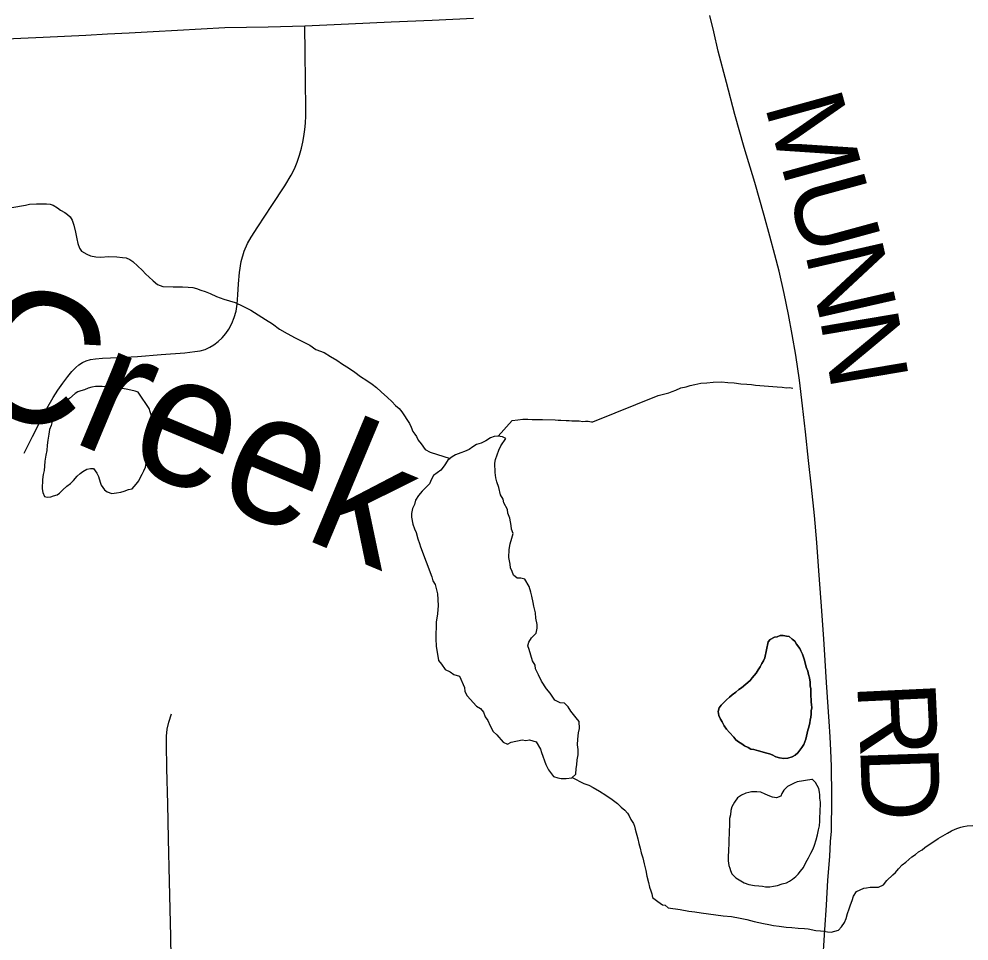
# Model space of a CAD drawing. Extents: x -11.4 to 84.1, y 11.1 to 59.
# Drawn here: x 31.454 to 32.145, y 42.32 to 42.991 of the extents above; entities that cross this region are included whole.
import ezdxf

# ---------------------------------------------------------------- set-up
doc = ezdxf.new("R2010")
doc.units = 0
for name, color, linetype in [('GM_X_Minor_Lake', 7, 'Continuous'), ('GM_X_Minor_River', 7, 'Continuous'), ('GM_X_Minor_River_Text', 7, 'Continuous'), ('GM_X_Township_Road', 7, 'Continuous'), ('GM_X_Township_Road_Text', 7, 'Continuous')]:
    doc.layers.add(name, color=color, linetype=linetype)

msp = doc.modelspace()

# ---------------------------------------------------------------- linework, layer by layer
at = {"layer": 'GM_X_Minor_Lake'}
for points in [[(31.54104, 42.7185), (31.54064, 42.71925), (31.53835, 42.71998), (31.5353, 42.72069), (31.53187, 42.72139), (31.52883, 42.72172), (31.5254, 42.72243), (31.52121, 42.72274), (31.51893, 42.72308), (31.51665, 42.72304), (31.51436, 42.72338), (31.51171, 42.72334), (31.50943, 42.7233), (31.50678, 42.72288), (31.50413, 42.72208), (31.50149, 42.72089), (31.49885, 42.72009), (31.49658, 42.71929), (31.4947, 42.71812), (31.49058, 42.71463), (31.48871, 42.71308), (31.48573, 42.70961), (31.48386, 42.70768), (31.48238, 42.70537), (31.4809, 42.70307), (31.47942, 42.70114), (31.47832, 42.69884), (31.47724, 42.69502), (31.47615, 42.69196), (31.47545, 42.68853), (31.47476, 42.68433), (31.47445, 42.68053), (31.47413, 42.67672), (31.47343, 42.67329), (31.47274, 42.66909), (31.47243, 42.66529), (31.4721, 42.66224), (31.47139, 42.65919), (31.47107, 42.65576), (31.4708, 42.64891), (31.47123, 42.64626), (31.47242, 42.64324), (31.47432, 42.64288), (31.47698, 42.64293), (31.47886, 42.64372)], [(31.54104, 42.7185), (31.54064, 42.71925), (31.53835, 42.71998), (31.5353, 42.72069), (31.53187, 42.72139), (31.52883, 42.72172), (31.5254, 42.72243), (31.52121, 42.72274), (31.51893, 42.72308), (31.51665, 42.72304), (31.51436, 42.72338), (31.51171, 42.72334), (31.50943, 42.7233), (31.50678, 42.72288), (31.50413, 42.72208), (31.50149, 42.72089), (31.49885, 42.72009), (31.49658, 42.71929), (31.4947, 42.71812), (31.49058, 42.71463), (31.48871, 42.71308), (31.48573, 42.70961), (31.48386, 42.70768), (31.48238, 42.70537), (31.4809, 42.70307), (31.47942, 42.70114), (31.47832, 42.69884), (31.47724, 42.69502), (31.47615, 42.69196), (31.47545, 42.68853), (31.47476, 42.68433), (31.47445, 42.68053), (31.47413, 42.67672), (31.47343, 42.67329), (31.47274, 42.66909), (31.47243, 42.66529), (31.4721, 42.66224), (31.47139, 42.65919), (31.47107, 42.65576), (31.4708, 42.64891), (31.47123, 42.64626), (31.47242, 42.64324), (31.47432, 42.64288), (31.47698, 42.64293), (31.47886, 42.64372), (31.48151, 42.64452), (31.48339, 42.64569), (31.48563, 42.64801), (31.48862, 42.65072), (31.49125, 42.65267), (31.49349, 42.65499), (31.4961, 42.65807), (31.49834, 42.66001), (31.50022, 42.66156), (31.50323, 42.66313), (31.50588, 42.66355), (31.50816, 42.66359), (31.51049, 42.66021), (31.51167, 42.65794), (31.51288, 42.65378), (31.51368, 42.65151), (31.51601, 42.64813), (31.51794, 42.64664), (31.52137, 42.64556), (31.52479, 42.64599), (31.52782, 42.64642), (31.53046, 42.64723), (31.53348, 42.64842), (31.53613, 42.64884), (31.53911, 42.65231), (31.54097, 42.65462), (31.54207, 42.65692), (31.54355, 42.65961), (31.54465, 42.66191), (31.54574, 42.66459), (31.54645, 42.66764), (31.54753, 42.67108), (31.54823, 42.67489), (31.54892, 42.67909), (31.54961, 42.6829), (31.54993, 42.68671), (31.55063, 42.68976), (31.5506, 42.69166), (31.55094, 42.69433), (31.55088, 42.69775), (31.55046, 42.7004), (31.55004, 42.70268), (31.54924, 42.70495), (31.54844, 42.70722), (31.54104, 42.7185)], [(31.47886, 42.64372), (31.48151, 42.64452), (31.48339, 42.64569), (31.48563, 42.64801), (31.48862, 42.65072), (31.49125, 42.65267), (31.49349, 42.65499), (31.4961, 42.65807), (31.49834, 42.66001), (31.50022, 42.66156), (31.50323, 42.66313), (31.50588, 42.66355), (31.50816, 42.66359), (31.51049, 42.66021), (31.51167, 42.65794), (31.51288, 42.65378), (31.51368, 42.65151), (31.51601, 42.64813), (31.51794, 42.64664), (31.52137, 42.64556), (31.52479, 42.64599), (31.52782, 42.64642), (31.53046, 42.64723), (31.53348, 42.64842), (31.53613, 42.64884), (31.53911, 42.65231), (31.54097, 42.65462), (31.54207, 42.65692), (31.54355, 42.65961), (31.54465, 42.66191), (31.54574, 42.66459), (31.54645, 42.66764), (31.54753, 42.67108), (31.54823, 42.67489), (31.54892, 42.67909), (31.54961, 42.6829), (31.54993, 42.68671), (31.55063, 42.68976), (31.5506, 42.69166), (31.55094, 42.69433), (31.55088, 42.69775), (31.55046, 42.7004), (31.55004, 42.70268), (31.54924, 42.70495), (31.54844, 42.70722), (31.54104, 42.7185)], [(31.80791, 42.68552), (31.80538, 42.68656), (31.80195, 42.68727), (31.7993, 42.68685), (31.79665, 42.68606), (31.79327, 42.68374), (31.78987, 42.68217), (31.78647, 42.68099), (31.78384, 42.67943), (31.78121, 42.6775), (31.77781, 42.67593), (31.77517, 42.67514), (31.77139, 42.67357), (31.76875, 42.67202), (31.76575, 42.6697), (31.76315, 42.66549), (31.76054, 42.66242), (31.75528, 42.65855), (31.7538, 42.65588), (31.75233, 42.65244), (31.7471, 42.64706), (31.74448, 42.64399), (31.74225, 42.64054), (31.74154, 42.63749), (31.74007, 42.63444), (31.73936, 42.63102), (31.7394, 42.62836), (31.74024, 42.62306), (31.74143, 42.61966), (31.74261, 42.61702), (31.74382, 42.61248), (31.74501, 42.60908), (31.74589, 42.60678)], [(31.75715, 42.5345), (31.75883, 42.5239), (31.76114, 42.52127), (31.76386, 42.51752), (31.76731, 42.51567), (31.76999, 42.51381), (31.77419, 42.51272), (31.77773, 42.50442), (31.77815, 42.5014), (31.77972, 42.49838), (31.78667, 42.49089), (31.78936, 42.48902), (31.79168, 42.4864), (31.79287, 42.483), (31.79481, 42.48037), (31.79638, 42.4766), (31.79872, 42.47246), (31.80142, 42.46984), (31.80606, 42.46459), (31.80912, 42.46311), (31.81176, 42.46467), (31.81971, 42.46629), (31.82237, 42.46595), (31.82503, 42.46637), (31.82999, 42.46492), (31.83311, 42.45965), (31.8339, 42.457), (31.83708, 42.44832), (31.83903, 42.44455), (31.84252, 42.43967), (31.84558, 42.43857), (31.84824, 42.43823), (31.85166, 42.43827), (31.85583, 42.43871), (31.85883, 42.44141), (31.85915, 42.44559), (31.85949, 42.44824), (31.85982, 42.45167), (31.86052, 42.45547), (31.86046, 42.45926), (31.86003, 42.46267), (31.86035, 42.46685), (31.86066, 42.47141), (31.86137, 42.47445), (31.86129, 42.47976), (31.85897, 42.48239), (31.8551, 42.48727), (31.85316, 42.49028), (31.85046, 42.4929), (31.84741, 42.49323), (31.84359, 42.49508), (31.84009, 42.50034), (31.83739, 42.50334), (31.83388, 42.50899), (31.83154, 42.51351), (31.82957, 42.51803), (31.82915, 42.52069), (31.8272, 42.52369), (31.8248, 42.53201), (31.824, 42.53465), (31.82472, 42.53732), (31.82657, 42.54038), (31.82994, 42.54384), (31.83064, 42.54764), (31.8306, 42.5503), (31.82977, 42.55484), (31.82934, 42.55863), (31.82813, 42.56355), (31.82771, 42.5662), (31.82688, 42.57074), (31.82607, 42.57377), (31.82487, 42.57792), (31.82175, 42.58319), (31.8187, 42.58391), (31.81604, 42.58387), (31.81335, 42.58611), (31.81255, 42.58876), (31.81137, 42.5914), (31.81095, 42.59405), (31.81012, 42.59897), (31.81041, 42.60467), (31.81111, 42.60885), (31.81219, 42.61304), (31.81327, 42.61647), (31.81209, 42.61949), (31.81167, 42.62214), (31.81083, 42.62744), (31.80925, 42.63121), (31.80921, 42.63387), (31.80648, 42.63876), (31.80606, 42.64141), (31.80412, 42.64442), (31.8029, 42.64972), (31.80132, 42.65387), (31.80051, 42.65689), (31.80008, 42.66068), (31.79997, 42.66751), (31.80031, 42.67017), (31.80287, 42.67704), (31.80434, 42.68009), (31.80791, 42.68552)], [(31.74589, 42.60678), (31.75411, 42.58492), (31.75491, 42.5819), (31.75647, 42.57926), (31.75809, 42.57246), (31.7586, 42.56412), (31.75831, 42.55804), (31.75726, 42.55195), (31.75706, 42.53981), (31.75715, 42.5345)], [(31.99865, 42.53758), (32.00021, 42.53934), (32.00323, 42.54092), (32.00512, 42.54133), (32.00738, 42.54213), (32.00966, 42.54216), (32.01195, 42.54182), (32.01385, 42.54147), (32.01616, 42.53961), (32.01809, 42.53812), (32.01926, 42.53585), (32.02159, 42.53285), (32.02238, 42.53096), (32.02356, 42.5287), (32.02516, 42.52417), (32.02638, 42.51924), (32.02757, 42.51622), (32.02799, 42.51395), (32.02879, 42.5113), (32.02922, 42.50826), (32.02927, 42.5056), (32.02969, 42.50333), (32.02973, 42.50067), (32.02978, 42.49801), (32.02982, 42.49573), (32.02985, 42.49383), (32.03026, 42.49193), (32.0303, 42.48965), (32.02996, 42.48737), (32.03, 42.48509), (32.02965, 42.4828), (32.02931, 42.48051), (32.02897, 42.4786), (32.02826, 42.47555), (32.02754, 42.47326), (32.02647, 42.46906), (32.02613, 42.46677), (32.0254, 42.46486), (32.02467, 42.46295), (32.02319, 42.46064), (32.02022, 42.45679), (32.01834, 42.45524), (32.01608, 42.45406), (32.01307, 42.45287), (32.01003, 42.45282), (32.00698, 42.45315), (32.00431, 42.45387), (32.00163, 42.45534), (31.99972, 42.45607), (31.99667, 42.45678), (31.99438, 42.45751), (31.99171, 42.45822), (31.98827, 42.45931), (31.98598, 42.45965), (31.98407, 42.46076), (31.98139, 42.46185), (31.97947, 42.46334), (31.97716, 42.46483), (31.97524, 42.46632), (31.97369, 42.46819), (31.97059, 42.47156), (31.96827, 42.47419), (31.96671, 42.47644), (31.96514, 42.47946), (31.96397, 42.48134), (31.96279, 42.48398), (31.96236, 42.48702), (31.96307, 42.48969), (31.96456, 42.49162), (31.96642, 42.49355), (31.96829, 42.49548), (31.97054, 42.49742), (31.97241, 42.49897), (31.97503, 42.50091), (31.97728, 42.50285), (31.97916, 42.50402), (31.98552, 42.50945), (31.98701, 42.51137), (31.98999, 42.51484), (31.99147, 42.51715), (31.99295, 42.51946), (31.99405, 42.52176), (31.99516, 42.52367), (31.99626, 42.52597), (31.99865, 42.53758)], [(32.01608, 42.45406), (32.01834, 42.45524), (32.02022, 42.45679), (32.02319, 42.46064), (32.02467, 42.46295), (32.0254, 42.46486), (32.02613, 42.46677), (32.02647, 42.46906), (32.02754, 42.47326), (32.02826, 42.47555), (32.02897, 42.4786), (32.02931, 42.48051), (32.02965, 42.4828), (32.03, 42.48509), (32.02996, 42.48737), (32.0303, 42.48965), (32.03026, 42.49193), (32.02985, 42.49383), (32.02982, 42.49573), (32.02978, 42.49801), (32.02973, 42.50067), (32.02969, 42.50333), (32.02927, 42.5056), (32.02922, 42.50826), (32.02879, 42.5113), (32.02799, 42.51395), (32.02757, 42.51622), (32.02638, 42.51924), (32.02516, 42.52417), (32.02356, 42.5287), (32.02238, 42.53096), (32.02159, 42.53285), (32.01926, 42.53585), (32.01809, 42.53812), (32.01616, 42.53961), (32.01385, 42.54147), (32.01195, 42.54182), (32.00966, 42.54216), (32.00738, 42.54213), (32.00512, 42.54133), (32.00323, 42.54092), (32.00021, 42.53934), (31.99865, 42.53758)], [(31.99865, 42.53758), (31.99626, 42.52597), (31.99516, 42.52367), (31.99405, 42.52176), (31.99295, 42.51946), (31.99147, 42.51715), (31.98999, 42.51484), (31.98701, 42.51137), (31.98552, 42.50945), (31.97916, 42.50402), (31.97728, 42.50285), (31.97503, 42.50091), (31.97241, 42.49897), (31.97054, 42.49742), (31.96829, 42.49548), (31.96642, 42.49355), (31.96456, 42.49162), (31.96307, 42.48969), (31.96236, 42.48702), (31.96279, 42.48398), (31.96397, 42.48134), (31.96514, 42.47946), (31.96671, 42.47644), (31.96827, 42.47419), (31.97059, 42.47156), (31.97369, 42.46819), (31.97524, 42.46632), (31.97716, 42.46483), (31.97947, 42.46334), (31.98139, 42.46185), (31.98407, 42.46076), (31.98598, 42.45965), (31.98827, 42.45931), (31.99171, 42.45822), (31.99438, 42.45751), (31.99667, 42.45678), (31.99972, 42.45607), (32.00163, 42.45534), (32.00431, 42.45387), (32.00698, 42.45315), (32.01003, 42.45282), (32.01307, 42.45287), (32.01608, 42.45406)], [(32.03042, 42.43757), (32.01981, 42.43587), (32.01755, 42.43469), (32.01567, 42.4339), (32.01265, 42.43233), (32.01004, 42.42963), (32.00856, 42.42732), (32.00783, 42.42541), (32.00481, 42.42422), (32.00177, 42.42455), (31.99986, 42.42528), (31.99642, 42.42674), (31.99335, 42.42821), (31.99031, 42.42854), (31.98651, 42.42848), (31.98462, 42.42807), (31.98235, 42.42765), (31.97933, 42.42608), (31.97633, 42.42413), (31.9741, 42.42105), (31.97226, 42.4176), (31.97155, 42.41493), (31.97122, 42.41188), (31.9705, 42.40921), (31.97054, 42.40693), (31.97059, 42.40389), (31.97027, 42.40046), (31.97004, 42.39171), (31.97008, 42.38943), (31.96973, 42.38752), (31.96977, 42.38524), (31.96945, 42.38182), (31.9695, 42.3784), (31.96994, 42.37498), (31.97073, 42.37309), (31.97115, 42.3712), (31.97232, 42.36894), (31.97503, 42.36594), (31.97887, 42.36372)], [(32.03042, 42.43757), (32.01981, 42.43587), (32.01755, 42.43469), (32.01567, 42.4339), (32.01265, 42.43233), (32.01004, 42.42963), (32.00856, 42.42732), (32.00783, 42.42541), (32.00481, 42.42422), (32.00177, 42.42455), (31.99986, 42.42528), (31.99642, 42.42674), (31.99335, 42.42821), (31.99031, 42.42854), (31.98651, 42.42848), (31.98462, 42.42807), (31.98235, 42.42765), (31.97933, 42.42608), (31.97633, 42.42413), (31.9741, 42.42105), (31.97226, 42.4176), (31.97155, 42.41493), (31.97122, 42.41188), (31.9705, 42.40921), (31.97054, 42.40693), (31.97059, 42.40389), (31.97027, 42.40046), (31.97004, 42.39171), (31.97008, 42.38943), (31.96973, 42.38752), (31.96977, 42.38524), (31.96945, 42.38182), (31.9695, 42.3784), (31.96994, 42.37498), (31.97073, 42.37309), (31.97115, 42.3712), (31.97232, 42.36894), (31.97503, 42.36594), (31.97887, 42.36372), (31.98117, 42.36224), (31.98461, 42.36116), (31.9888, 42.36046), (31.99184, 42.36013), (31.99451, 42.3598), (31.99679, 42.35945), (31.99983, 42.3595), (32.00248, 42.35993), (32.00551, 42.36036), (32.00891, 42.36155), (32.01193, 42.36236), (32.01419, 42.36354), (32.01645, 42.3651), (32.01869, 42.36704), (32.02057, 42.36859), (32.02205, 42.37089), (32.02428, 42.37359), (32.02612, 42.37704), (32.02796, 42.3805), (32.0298, 42.38395), (32.03127, 42.38701), (32.03236, 42.38969), (32.03344, 42.39351), (32.03451, 42.39733), (32.03522, 42.40077), (32.03592, 42.40382), (32.03625, 42.40725), (32.03619, 42.41029), (32.03652, 42.41333), (32.03677, 42.42094), (32.03634, 42.42398), (32.0363, 42.42626), (32.03589, 42.42815), (32.03547, 42.43081), (32.03429, 42.43307), (32.03311, 42.43533), (32.0308, 42.43757), (32.03042, 42.43757)], [(31.97887, 42.36372), (31.98117, 42.36224), (31.98461, 42.36116), (31.9888, 42.36046), (31.99184, 42.36013), (31.99451, 42.3598), (31.99679, 42.35945), (31.99983, 42.3595), (32.00248, 42.35993), (32.00551, 42.36036), (32.00891, 42.36155), (32.01193, 42.36236), (32.01419, 42.36354), (32.01645, 42.3651), (32.01869, 42.36704), (32.02057, 42.36859), (32.02205, 42.37089), (32.02428, 42.37359), (32.02612, 42.37704), (32.02796, 42.3805), (32.0298, 42.38395), (32.03127, 42.38701), (32.03236, 42.38969), (32.03344, 42.39351), (32.03451, 42.39733), (32.03522, 42.40077), (32.03592, 42.40382), (32.03625, 42.40725), (32.03619, 42.41029), (32.03652, 42.41333), (32.03677, 42.42094), (32.03634, 42.42398), (32.0363, 42.42626), (32.03589, 42.42815), (32.03547, 42.43081), (32.03429, 42.43307), (32.03311, 42.43533), (32.0308, 42.43757), (32.03042, 42.43757)]]:
    msp.add_lwpolyline(points, dxfattribs=at)
at = {"layer": 'GM_X_Minor_River'}
for points in [[(31.44874, 42.85348), (31.45859, 42.85517), (31.46161, 42.85598), (31.46655, 42.85606), (31.47377, 42.85617), (31.47643, 42.85584), (31.47872, 42.85512), (31.48179, 42.85327), (31.4841, 42.8514), (31.48717, 42.84993), (31.48909, 42.84844), (31.49102, 42.84657), (31.49258, 42.84432), (31.49378, 42.84053), (31.495, 42.83561), (31.49584, 42.83068), (31.49666, 42.82727), (31.49786, 42.82387), (31.49941, 42.82162), (31.50325, 42.8194), (31.50593, 42.8183), (31.50974, 42.8176), (31.51316, 42.81728), (31.51923, 42.81776), (31.52493, 42.81747), (31.52912, 42.81716), (31.53178, 42.81682), (31.53446, 42.81573), (31.53676, 42.81424), (31.54024, 42.81088), (31.54333, 42.80789), (31.54603, 42.80489), (31.54835, 42.80303), (31.55143, 42.80004), (31.55452, 42.79742), (31.55834, 42.79597), (31.56594, 42.79571), (31.56936, 42.79577), (31.57277, 42.79582), (31.57696, 42.79551), (31.58038, 42.79519), (31.58305, 42.79447), (31.58611, 42.79338), (31.58917, 42.79229), (31.59299, 42.79083), (31.59758, 42.78863), (31.60293, 42.78681), (31.61095, 42.78428), (31.61669, 42.78172), (31.62244, 42.77877), (31.62781, 42.77543), (31.63318, 42.7721), (31.63818, 42.76876), (31.64318, 42.76504), (31.64893, 42.76171), (31.65468, 42.75876), (31.66043, 42.75582), (31.66541, 42.75324), (31.66964, 42.75027), (31.67575, 42.74808), (31.68036, 42.74512), (31.68496, 42.74253), (31.68918, 42.73956), (31.69341, 42.73697), (31.69802, 42.73362), (31.70225, 42.73065), (31.70686, 42.72768), (31.7107, 42.72508), (31.71378, 42.72247), (31.71725, 42.71949), (31.72188, 42.71538), (31.72497, 42.71239), (31.72768, 42.70939), (31.73037, 42.70716), (31.73231, 42.70491), (31.73426, 42.7019), (31.73582, 42.69926), (31.73777, 42.69625), (31.73896, 42.69361), (31.74015, 42.69059), (31.7417, 42.68871), (31.74287, 42.68683), (31.74405, 42.68419), (31.74638, 42.68156), (31.74911, 42.67743), (31.75293, 42.67559), (31.76732, 42.6709)], [(31.87106, 42.69768), (31.9186, 42.7167), (31.92352, 42.71792), (31.92654, 42.71874), (31.92881, 42.71953), (31.93145, 42.72072), (31.93522, 42.7223), (31.939, 42.72312), (31.94203, 42.72393), (31.94543, 42.72475), (31.9496, 42.72558), (31.95415, 42.72603), (31.9587, 42.72649), (31.96477, 42.72659), (31.96933, 42.72628), (31.9739, 42.72597), (31.97885, 42.7253), (31.98303, 42.72499), (31.98645, 42.72466), (31.9895, 42.72433), (31.99254, 42.724), (32.00205, 42.72339), (32.00509, 42.72306), (32.0089, 42.72275), (32.01194, 42.72242), (32.01422, 42.72245), (32.0165, 42.72211)], [(31.80228, 42.6872), (31.81256, 42.69862), (31.81673, 42.69906), (31.82014, 42.6995), (31.82394, 42.69956), (31.82698, 42.69924), (31.8304, 42.69929), (31.83457, 42.69936), (31.84369, 42.69913), (31.84598, 42.69878), (31.84788, 42.69882), (31.85168, 42.6985), (31.85396, 42.69853), (31.85586, 42.69819), (31.85776, 42.69822), (31.86118, 42.69827), (31.86384, 42.69794), (31.86574, 42.69797), (31.86764, 42.698), (31.8703, 42.69766), (31.87106, 42.69768)], [(31.85616, 42.439), (31.86449, 42.43446), (31.86831, 42.43339), (31.87137, 42.43154), (31.87598, 42.42895), (31.88058, 42.42599), (31.88519, 42.42302), (31.88904, 42.42004), (31.89174, 42.41742), (31.89444, 42.41518), (31.89638, 42.41294), (31.89755, 42.41106), (31.89873, 42.40841), (31.90068, 42.4054), (31.90147, 42.40352), (31.90189, 42.40124), (31.9039, 42.39443), (31.90472, 42.39102), (31.90554, 42.38761), (31.90636, 42.3842), (31.90756, 42.38042), (31.90839, 42.37625), (31.90961, 42.37133), (31.91044, 42.36716), (31.91166, 42.36262), (31.91248, 42.35921), (31.91328, 42.35656), (31.91408, 42.35429), (31.9145, 42.35164), (31.91835, 42.34866), (31.92181, 42.34644), (31.92371, 42.34609), (31.92602, 42.34422), (31.93478, 42.34285), (31.94088, 42.34181), (31.94544, 42.34112), (31.95001, 42.34044), (31.95534, 42.33976), (31.96067, 42.33909), (31.966, 42.33842), (31.97209, 42.33776), (31.97818, 42.33672), (31.98314, 42.33566), (31.98848, 42.33422), (31.99534, 42.33282), (31.99915, 42.33212), (32.00258, 42.33141), (32.00677, 42.33072), (32.01172, 42.33004), (32.0159, 42.32973), (32.02047, 42.32942), (32.02503, 42.32912), (32.02769, 42.32878), (32.03341, 42.32774), (32.03683, 42.32741), (32.03912, 42.32707), (32.04178, 42.32673), (32.04445, 42.3264), (32.04974, 42.328), (32.05198, 42.33032), (32.0542, 42.3334), (32.05529, 42.33646), (32.05637, 42.3399), (32.05746, 42.34334), (32.05854, 42.3464), (32.05963, 42.34946), (32.06072, 42.35252), (32.06294, 42.35598), (32.06558, 42.35716), (32.06822, 42.35834), (32.07011, 42.35875), (32.07276, 42.35918), (32.07504, 42.35922), (32.07694, 42.35925), (32.07883, 42.35928), (32.08261, 42.36086), (32.08483, 42.36394), (32.08932, 42.3682), (32.09119, 42.36975), (32.09343, 42.37245), (32.09603, 42.37553), (32.09866, 42.37747), (32.1009, 42.37941), (32.10315, 42.38135), (32.10578, 42.38291), (32.10803, 42.38485), (32.11066, 42.38642), (32.11253, 42.38797), (32.1223, 42.39459), (32.12568, 42.39655), (32.12907, 42.3985), (32.13208, 42.40007), (32.13472, 42.40126), (32.13661, 42.40205), (32.13887, 42.40284), (32.14076, 42.40326), (32.14341, 42.40368), (32.14758, 42.40413)]]:
    msp.add_lwpolyline(points, dxfattribs=at)
at = {"layer": 'GM_X_Township_Road'}
for points in [[(31.43912, 42.9758), (31.45526, 42.97651), (31.47138, 42.97722), (31.5024, 42.97889), (31.51814, 42.97974), (31.53387, 42.98058), (31.55151, 42.98154), (31.56915, 42.98249), (31.58636, 42.98339), (31.60356, 42.98429), (31.61935, 42.98462), (31.63513, 42.98495), (31.66176, 42.98563), (31.67762, 42.98628), (31.69349, 42.98692), (31.72453, 42.98836), (31.7544, 42.98976), (31.78427, 42.99114)], [(32.03815, 42.30159), (32.03991, 42.32813), (32.04103, 42.34618), (32.04215, 42.36423), (32.04352, 42.3814), (32.0441, 42.39242), (32.04459, 42.39984), (32.04479, 42.40764), (32.04489, 42.41506), (32.04499, 42.4252), (32.04459, 42.44725), (32.0442, 42.45866), (32.04364, 42.46861), (32.04302, 42.47974), (32.04108, 42.50813), (32.0401, 42.52393), (32.03913, 42.53973), (32.03717, 42.56667), (32.03561, 42.5893), (32.03396, 42.60988), (32.0323, 42.62949), (32.03025, 42.65008), (32.0281, 42.66939), (32.02586, 42.69027), (32.02372, 42.70929), (32.02137, 42.72783), (32.01874, 42.74597), (32.0161, 42.761), (32.01338, 42.77573), (32.01035, 42.79085), (32.00664, 42.80724), (32.00352, 42.81915), (31.99991, 42.83251), (31.99582, 42.84756), (31.98904, 42.87175), (31.98128, 42.89709), (31.97435, 42.921), (31.9683, 42.94431), (31.96225, 42.96724), (31.95913, 42.98109), (31.9562, 42.99319)], [(31.45755, 42.6749), (31.46363, 42.68694), (31.47412, 42.70721), (31.47865, 42.71532), (31.48219, 42.7206), (31.48568, 42.7257), (31.48926, 42.73053), (31.49239, 42.73428), (31.49516, 42.73714), (31.49739, 42.73911), (31.50007, 42.74072), (31.50276, 42.74206), (31.50598, 42.74295), (31.50955, 42.74349), (31.51456, 42.74385), (31.52618, 42.74447), (31.54002, 42.7452), (31.55728, 42.74653), (31.57455, 42.74787), (31.58161, 42.74868), (31.58563, 42.7493), (31.5892, 42.75029), (31.5927, 42.7519), (31.59555, 42.75359), (31.59869, 42.75592), (31.60154, 42.7586), (31.60432, 42.76182), (31.60646, 42.76504), (31.60865, 42.76916), (31.61045, 42.77355), (31.61173, 42.77813), (31.61249, 42.78314), (31.61312, 42.78993), (31.61348, 42.79798), (31.6141, 42.80612), (31.61554, 42.81425), (31.61759, 42.82158), (31.62009, 42.8273), (31.6226, 42.83186), (31.62752, 42.83937), (31.6378, 42.85502), (31.64709, 42.86914), (31.65183, 42.87701), (31.65416, 42.88157), (31.65613, 42.8863), (31.65791, 42.8914), (31.65934, 42.8965), (31.66031, 42.90107), (31.66107, 42.90517), (31.66176, 42.91018), (31.6622, 42.91474), (31.66239, 42.92001), (31.66249, 42.9251), (31.66226, 42.94549), (31.66202, 42.96587), (31.66176, 42.98563)], [(31.57112, 42.01217), (31.57055, 42.03629), (31.56999, 42.06042), (31.56935, 42.09148), (31.56876, 42.11981), (31.56818, 42.14813), (31.56752, 42.17919), (31.56695, 42.20641), (31.56637, 42.23362), (31.56559, 42.26288), (31.56482, 42.29214), (31.5642, 42.32321), (31.5638, 42.34327), (31.5634, 42.36333), (31.56266, 42.3944), (31.56205, 42.41989), (31.56143, 42.44537), (31.56106, 42.46334), (31.56112, 42.469), (31.56162, 42.47419), (31.56273, 42.47924), (31.5647, 42.48516)]]:
    msp.add_lwpolyline(points, dxfattribs=at)

# ---------------------------------------------------------------- texts
at = {"layer": 'GM_X_Minor_River_Text'}
msp.add_text('Creek', height=0.094755, rotation=337.32815, dxfattribs=at).set_placement((31.40591, 42.71919))
at = {"layer": 'GM_X_Township_Road_Text'}
for s, rotation, p in [('M', 285.39527, (31.99581, 42.92807)), ('U', 285.24586, (32.01217, 42.86866)), ('N', 282.87613, (32.02517, 42.82102)), ('N', 279.58869, (32.03614, 42.77312)), ('R', 272.70961, (32.06335, 42.50738)), ('D', 271.91644, (32.06554, 42.46097))]:
    msp.add_text(s, height=0.05682, rotation=rotation, dxfattribs=at).set_placement(p)

doc.saveas('drawing.dxf')
